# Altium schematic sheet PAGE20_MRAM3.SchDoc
size 381 x 381 mm; SheetNumber: 21; SheetTotal: 28
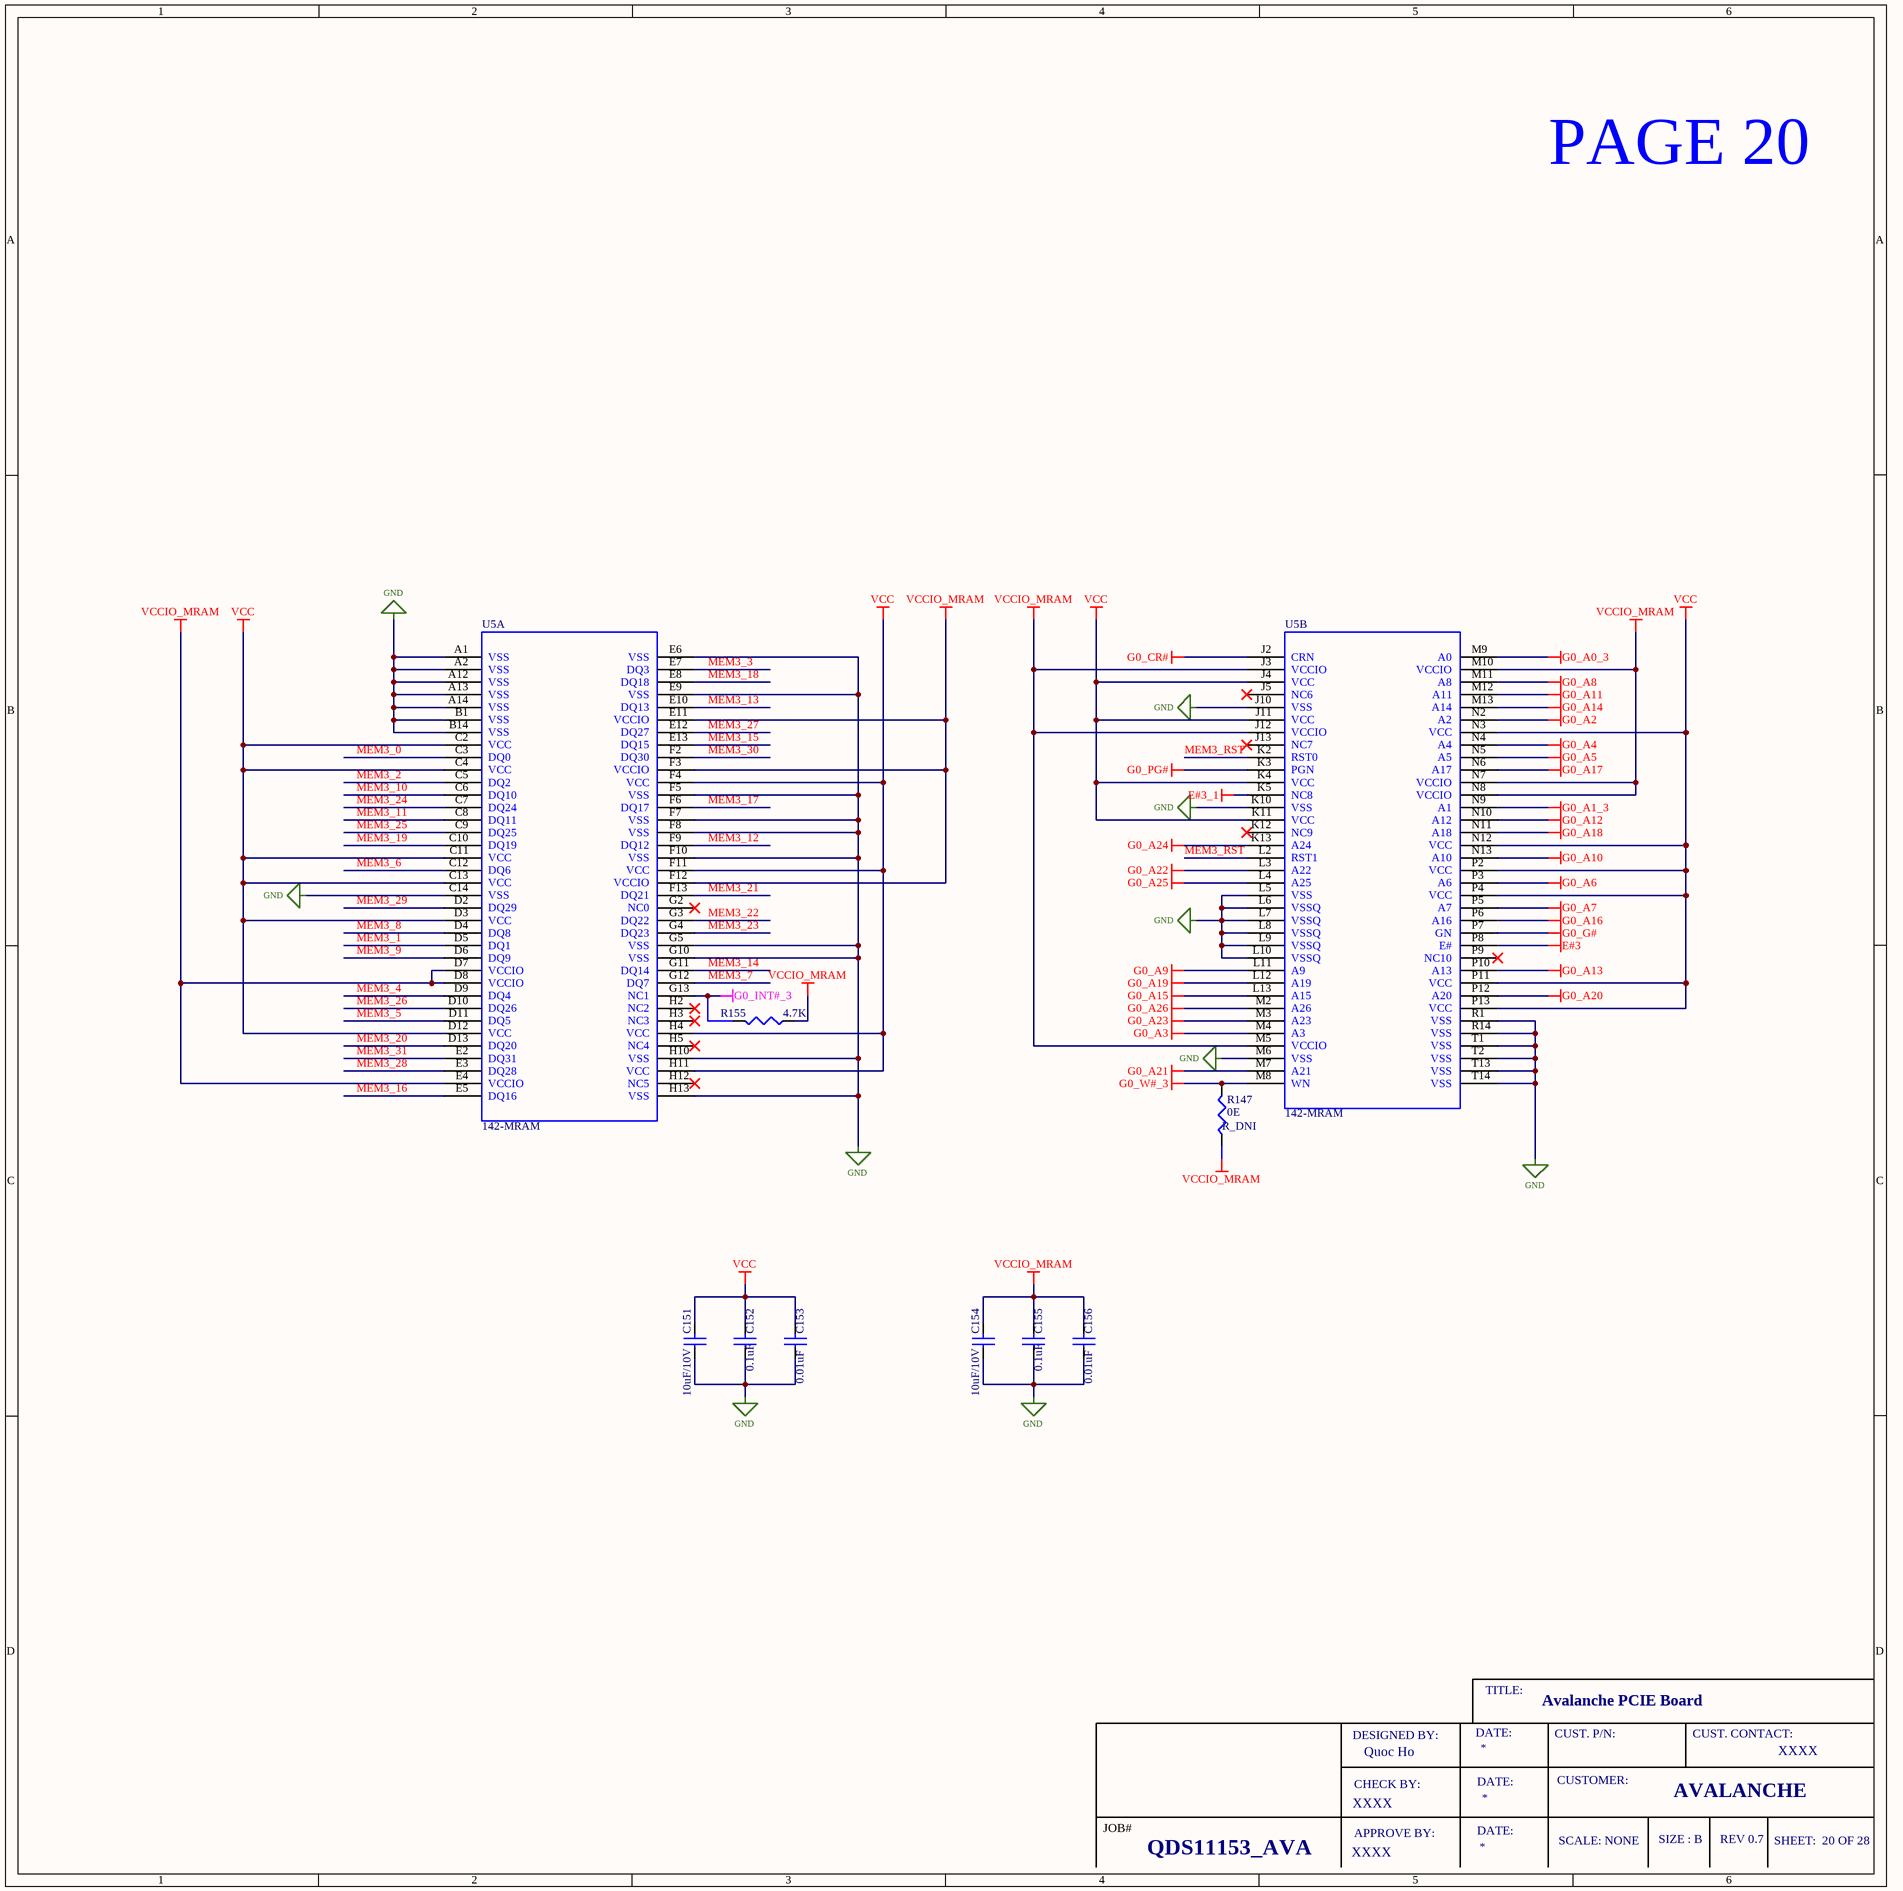
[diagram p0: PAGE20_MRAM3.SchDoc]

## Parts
C151  10uF/10V  [CN_0402]
C152  0.1uF  [CN_0402]
C153  0.01uF  [CN_0402]
C154  10uF/10V  [CN_0402]
C155  0.1uF  [CN_0402]
C156  0.01uF  [CN_0402]
R147  0E  [RN_0402]
R155  4.7K  [RN_0402]
U5  142-MRAM  [142-MRAM]  (parts A,B of 2)

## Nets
E#3: U5.P8(E#)
E#3_1: U5.K5(NC8)
G0_A0_3: U5.M9(A0)
G0_A1_3: U5.N9(A1)
G0_A2: U5.N2(A2)
G0_A3: U5.M4(A3)
G0_A4: U5.N4(A4)
G0_A5: U5.N5(A5)
G0_A6: U5.P3(A6)
G0_A7: U5.P5(A7)
G0_A8: U5.M11(A8)
G0_A9: U5.L11(A9)
G0_A10: U5.N13(A10)
G0_A11: U5.M12(A11)
G0_A12: U5.N10(A12)
G0_A13: U5.P10(A13)
G0_A14: U5.M13(A14)
G0_A15: U5.L13(A15)
G0_A16: U5.P6(A16)
G0_A17: U5.N6(A17)
G0_A18: U5.N11(A18)
G0_A19: U5.L12(A19)
G0_A20: U5.P12(A20)
G0_A21: U5.M7(A21)
G0_A22: U5.L3(A22)
G0_A23: U5.M3(A23)
G0_A24: U5.K13(A24)
G0_A25: U5.L4(A25)
G0_A26: U5.M2(A26)
G0_CR#: U5.J2(CRN)
G0_G#: U5.P7(GN)
G0_INT#_3: R155.2 U5.G13(NC1)
G0_PG#: U5.K3(PGN)
G0_W#_3: R147.2 U5.M8(WN)
GND: C151.1 C152.1 C153.1 C154.1 C155.1 C156.1 U5.A1(VSS) U5.A2(VSS) U5.A12(VSS) U5.A13(VSS) U5.A14(VSS) U5.B1(VSS) U5.B14(VSS) U5.C14(VSS) U5.E6(VSS) U5.E9(VSS) U5.F5(VSS) U5.F7(VSS) U5.F8(VSS) U5.F10(VSS) U5.G5(VSS) U5.G10(VSS) U5.H10(VSS) U5.H13(VSS) U5.J10(VSS) U5.K10(VSS) U5.L5(VSS) U5.L6(VSSQ) U5.L7(VSSQ) U5.L8(VSSQ) U5.L9(VSSQ) U5.L10(VSSQ) U5.M6(VSS) U5.R1(VSS) U5.R14(VSS) U5.T1(VSS) U5.T2(VSS) U5.T13(VSS) U5.T14(VSS)
VCC: C151.2 C152.2 C153.2 U5.C2(VCC) U5.C4(VCC) U5.C11(VCC) U5.C13(VCC) U5.D3(VCC) U5.D12(VCC) U5.F4(VCC) U5.F11(VCC) U5.H4(VCC) U5.H11(VCC) U5.J4(VCC) U5.J11(VCC) U5.K4(VCC) U5.K11(VCC) U5.N3(VCC) U5.N12(VCC) U5.P2(VCC) U5.P4(VCC) U5.P11(VCC) U5.P13(VCC)
VCCIO_MRAM: C154.2 C155.2 C156.2 R147.1 R155.1 U5.D7(VCCIO) U5.D8(VCCIO) U5.E4(VCCIO) U5.E11(VCCIO) U5.F3(VCCIO) U5.F12(VCCIO) U5.J3(VCCIO) U5.J12(VCCIO) U5.M5(VCCIO) U5.M10(VCCIO) U5.N7(VCCIO) U5.N8(VCCIO)
MEM3_0: U5.C3(DQ0)
MEM3_1: U5.D5(DQ1)
MEM3_2: U5.C5(DQ2)
MEM3_3: U5.E7(DQ3)
MEM3_4: U5.D9(DQ4)
MEM3_5: U5.D11(DQ5)
MEM3_6: U5.C12(DQ6)
MEM3_7: U5.G12(DQ7)
MEM3_8: U5.D4(DQ8)
MEM3_9: U5.D6(DQ9)
MEM3_10: U5.C6(DQ10)
MEM3_11: U5.C8(DQ11)
MEM3_12: U5.F9(DQ12)
MEM3_13: U5.E10(DQ13)
MEM3_14: U5.G11(DQ14)
MEM3_15: U5.E13(DQ15)
MEM3_16: U5.E5(DQ16)
MEM3_17: U5.F6(DQ17)
MEM3_18: U5.E8(DQ18)
MEM3_19: U5.C10(DQ19)
MEM3_20: U5.D13(DQ20)
MEM3_21: U5.F13(DQ21)
MEM3_22: U5.G3(DQ22)
MEM3_23: U5.G4(DQ23)
MEM3_24: U5.C7(DQ24)
MEM3_25: U5.C9(DQ25)
MEM3_26: U5.D10(DQ26)
MEM3_27: U5.E12(DQ27)
MEM3_28: U5.E3(DQ28)
MEM3_29: U5.D2(DQ29)
MEM3_30: U5.F2(DQ30)
MEM3_31: U5.E2(DQ31)
MEM3_RST: U5.K2(RST0) U5.L2(RST1)

Not connected (* = marked no-connect by the designer): U5 G2(NC0)* H2(NC2)* H3(NC3)* H5(NC4)* H12(NC5)* J5(NC6)* J13(NC7)* K12(NC9)* P9(NC10)*

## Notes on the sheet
- PAGE 20
- TITLE:
- Avalanche PCIE Board
- DESIGNED BY:
- CHECK BY:
- Quoc Ho
- DATE:
- CUST. P/N:
- CUSTOMER:
- CUST. CONTACT:
- XXXX
- JOB#
- APPROVE BY:
- SCALE: NONE
- SIZE : B
- AVALANCHE
- REV 0.7
- SHEET:  20 OF 28
- QDS11153_AVA

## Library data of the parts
C151 = CAP: CAP CER 10UF 10V X5R 0402; Manufacturer Part Number: GRM155R61A106ME11D; Manufacturer: Murata Electronics
C152 C155 = CAP: CAP CER 0.1UF 50V X7R 0402; Manufacturer: Murata Electronics; Manufacturer Part Number: GCM155R71H104KE02J
C153 C156 = CAP: 0.01 µF, 25 V, 0402 [1005 Metric], ± 10%, X7R; Manufacturer: YAGEO; Manufacturer Part Number: CC0402JRX7R8BB103
C154 = CAP: CAP CER 10UF 10V X5R 0402; Manufacturer: Murata Electronics; Manufacturer Part Number: GRM155R61A106ME11D
R147 = RES: RES 0 OHM JUMPER 1/16W 0402; Manufacturer Part Number: RC0402FR-070RL; Manufacturer: YAGEO
R155 = RES: RES 4.7K OHM 1% 1/16W 0402; Manufacturer Part Number: RC0402FR-134K7L; Manufacturer: YAGEO
U5 = 142-MRAM: IC 142-MRAM MEMORY; Manufacturer: Avalanche Technology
